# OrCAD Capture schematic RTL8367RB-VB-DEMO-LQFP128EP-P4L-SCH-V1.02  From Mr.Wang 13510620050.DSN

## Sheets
1 01_RTL8367RB-VB_Block_Diagram: title: RTL8367RB-VB Demo-Boaard Block Diagram; rev: v.1.02
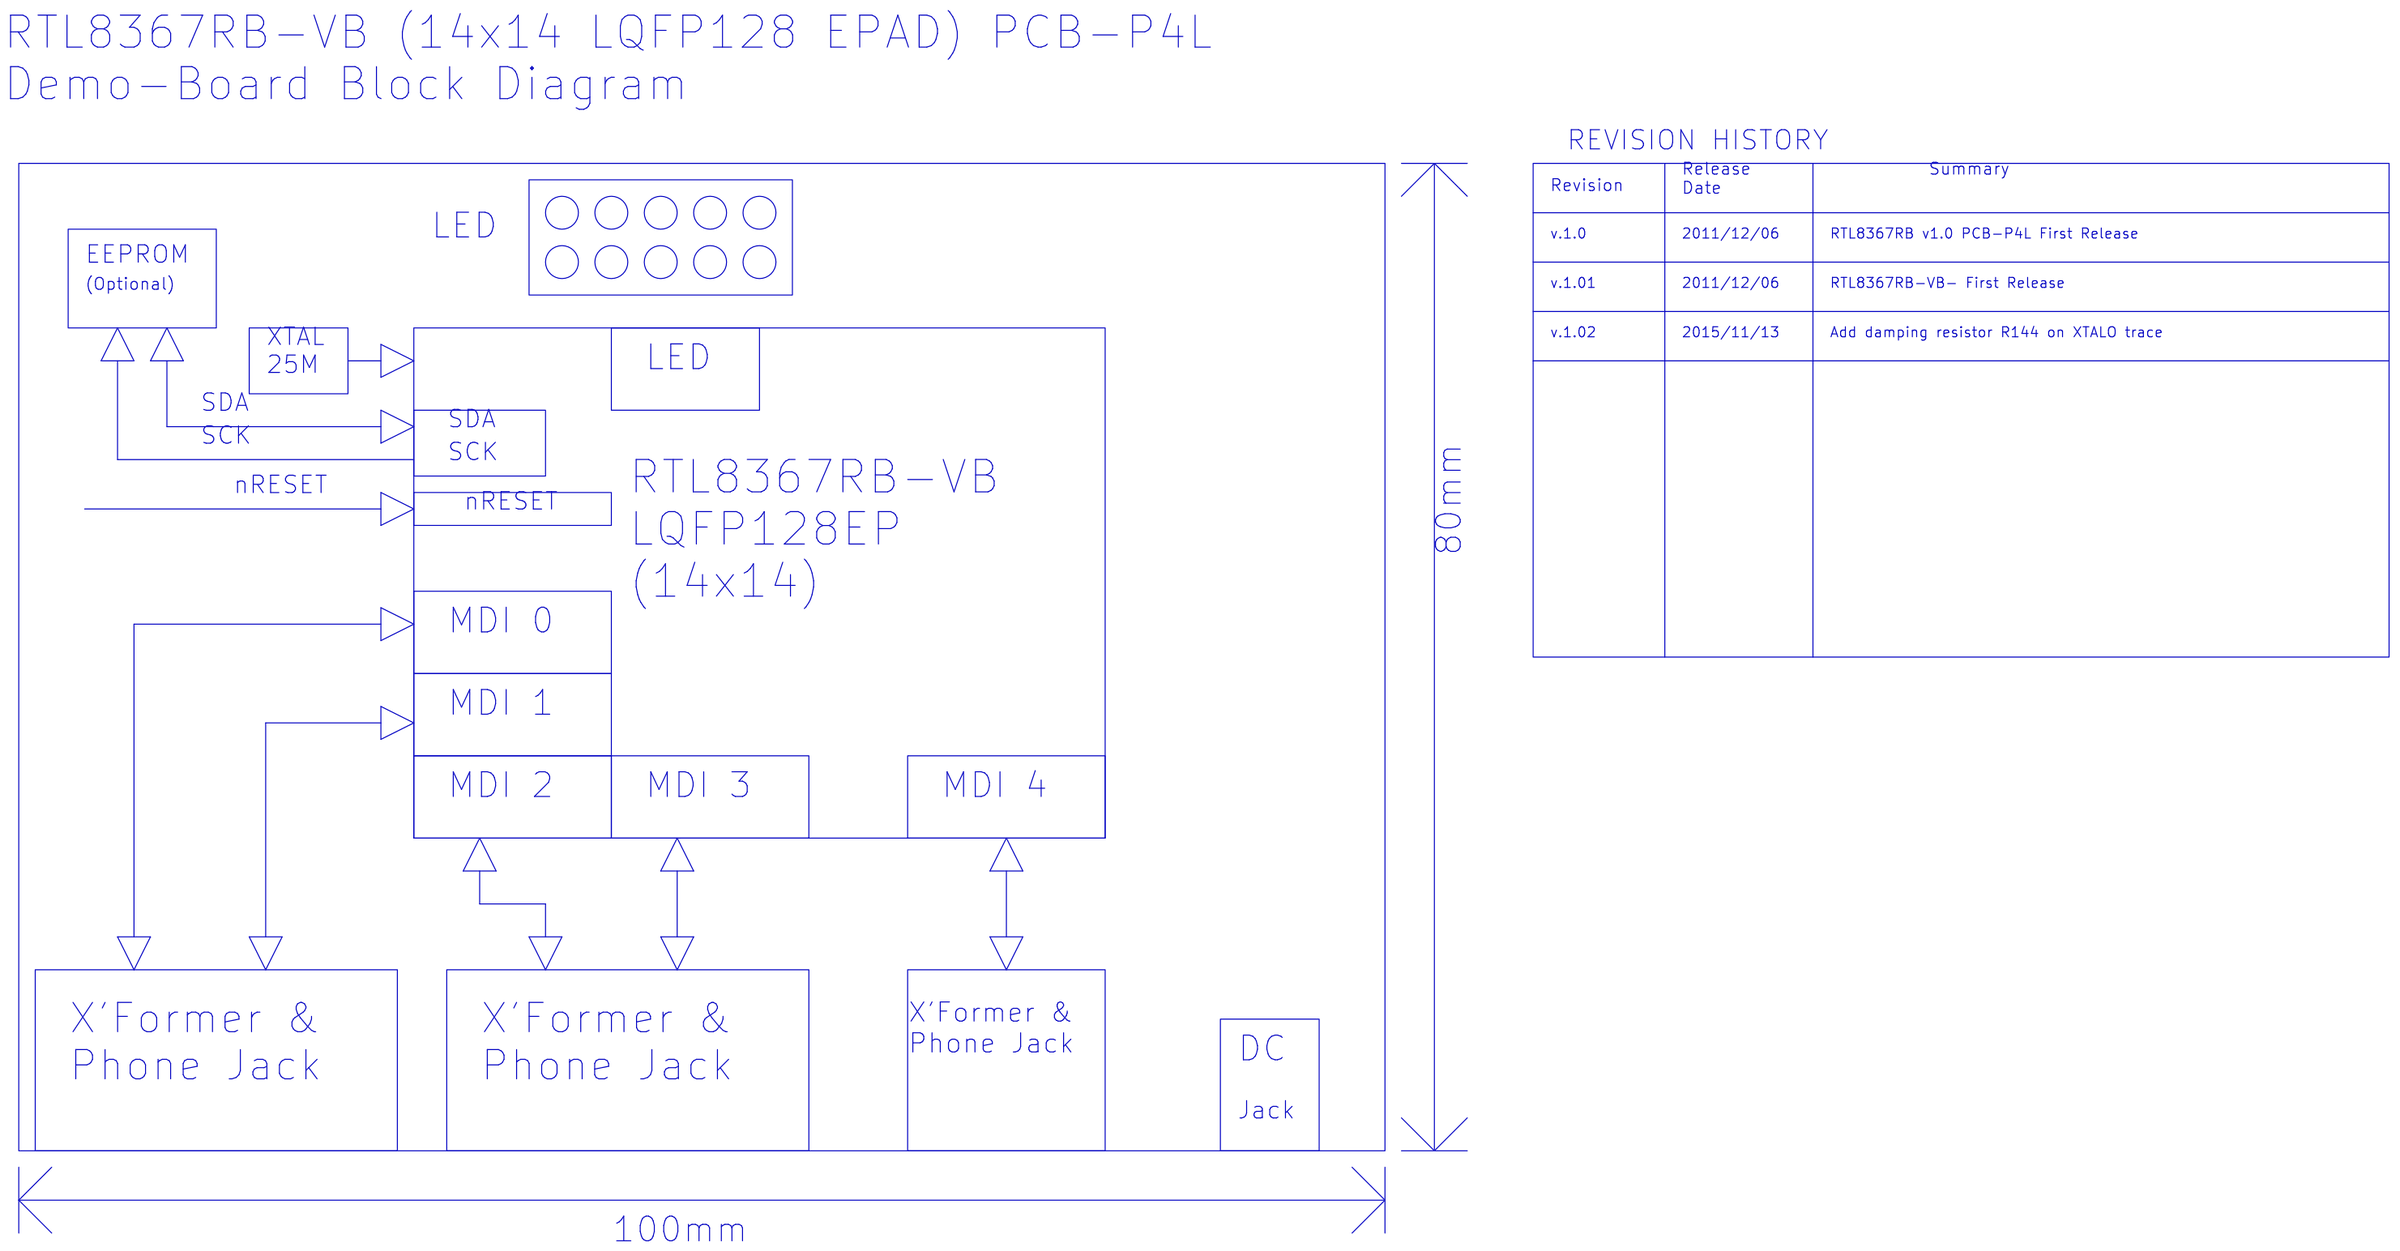
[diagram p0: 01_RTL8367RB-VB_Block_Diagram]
2 02_Power: size B; title: Power
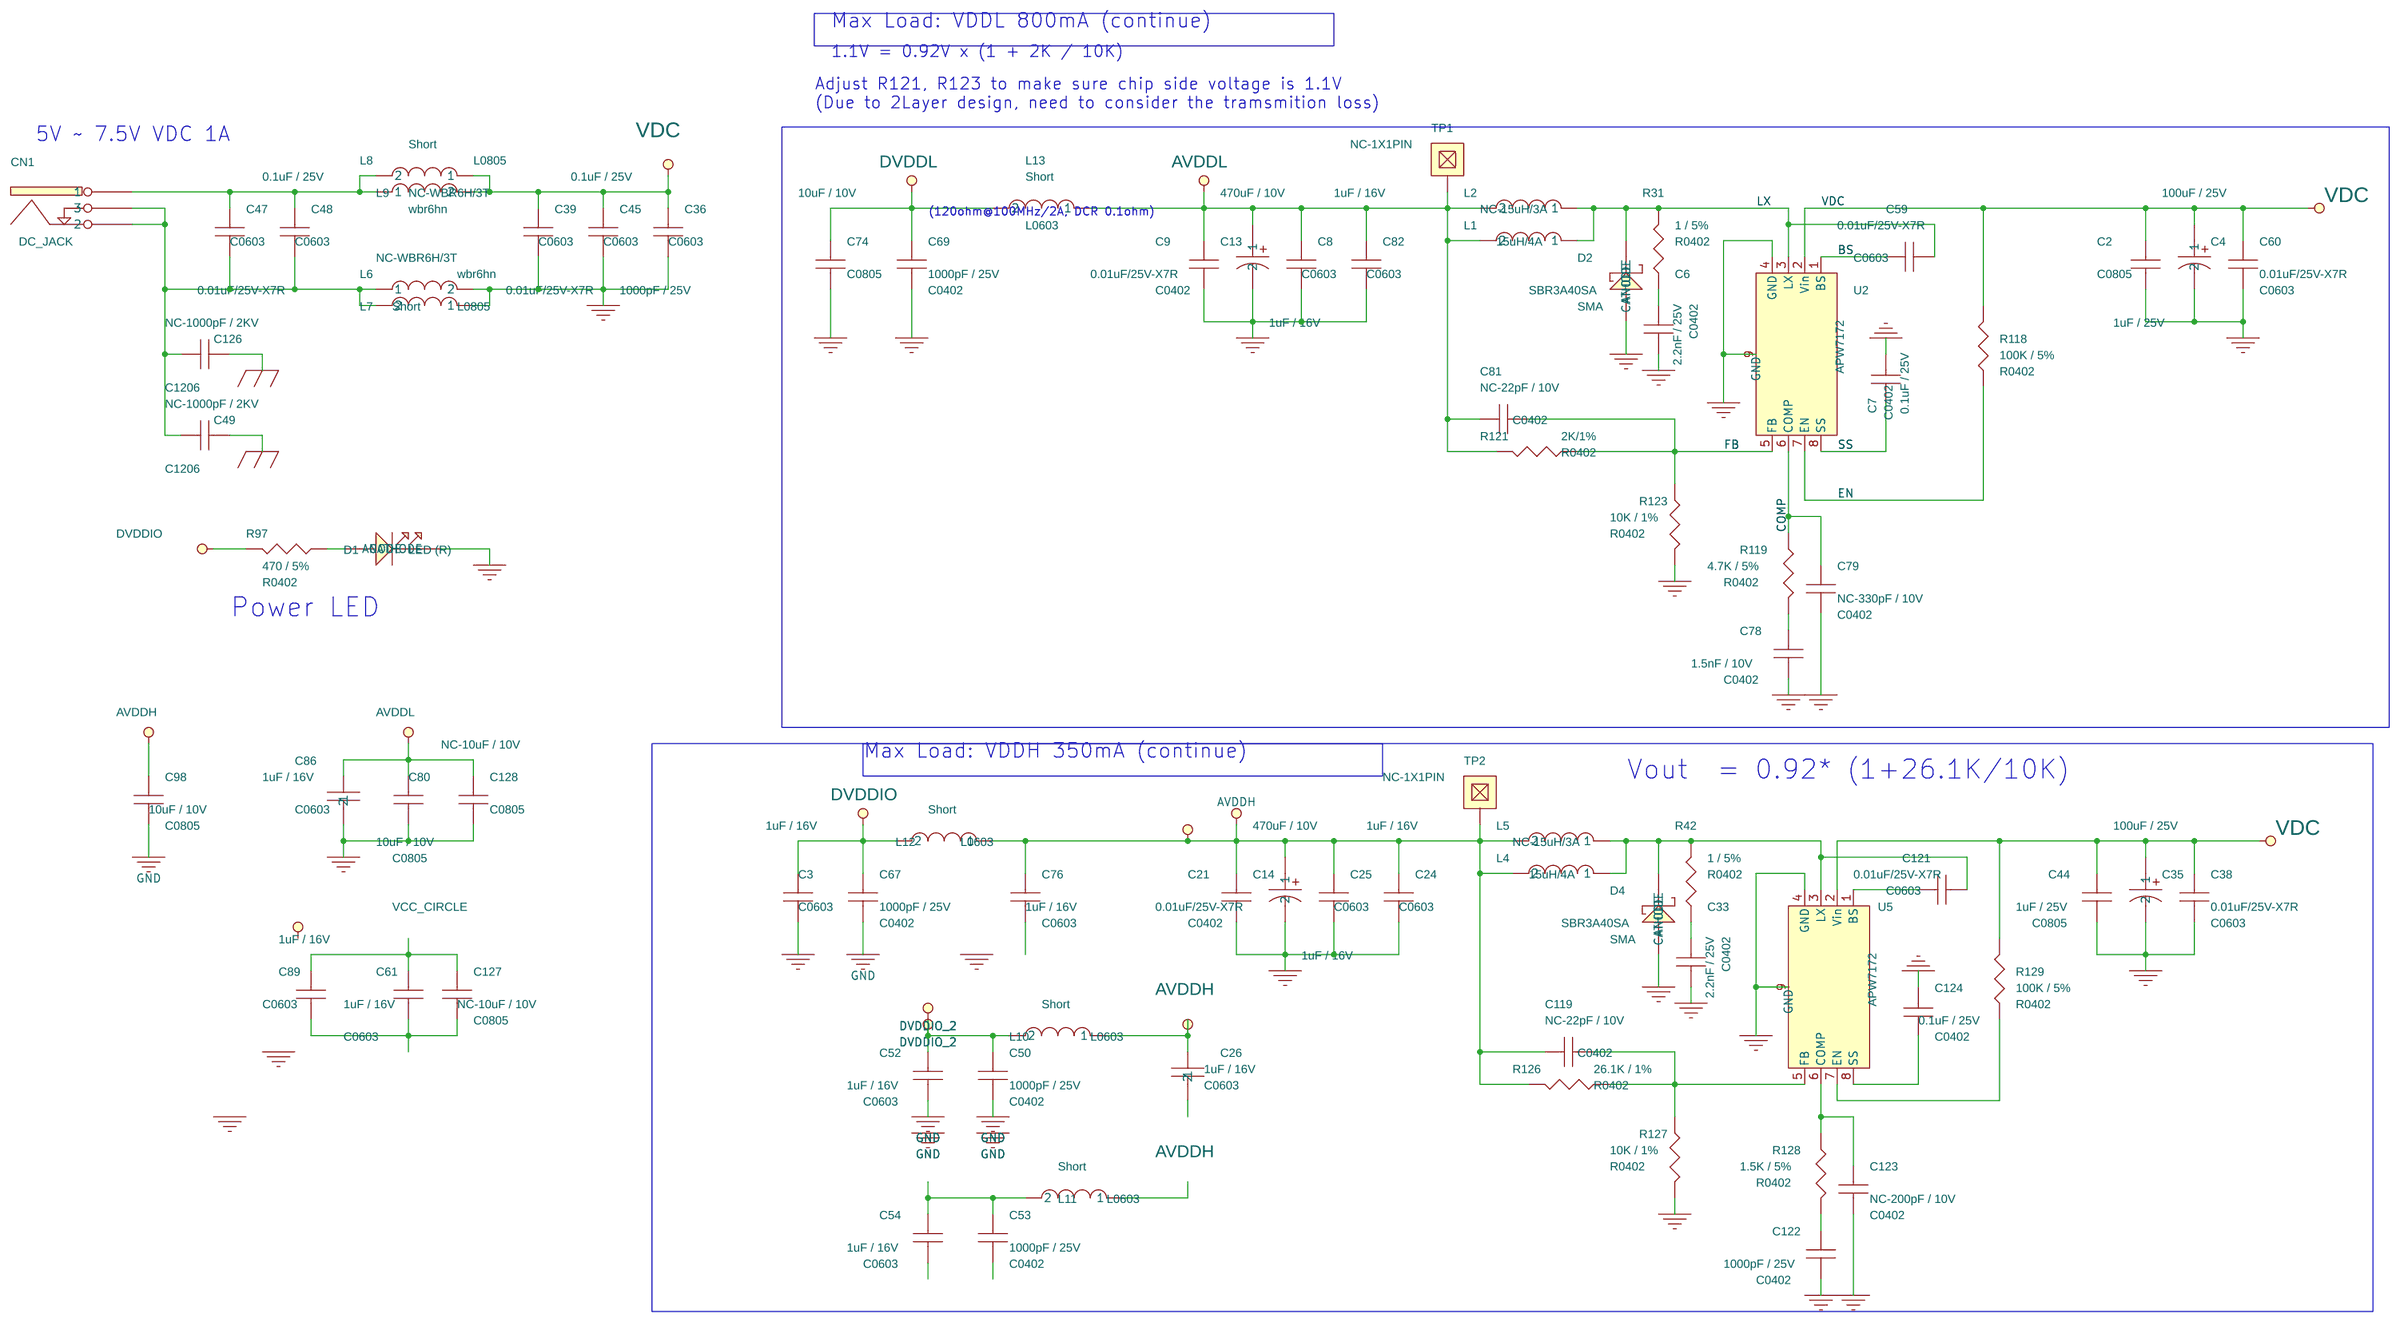
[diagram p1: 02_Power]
3 03_RTL8367RB-VB: size Custom; title: RTL8367RB-VB
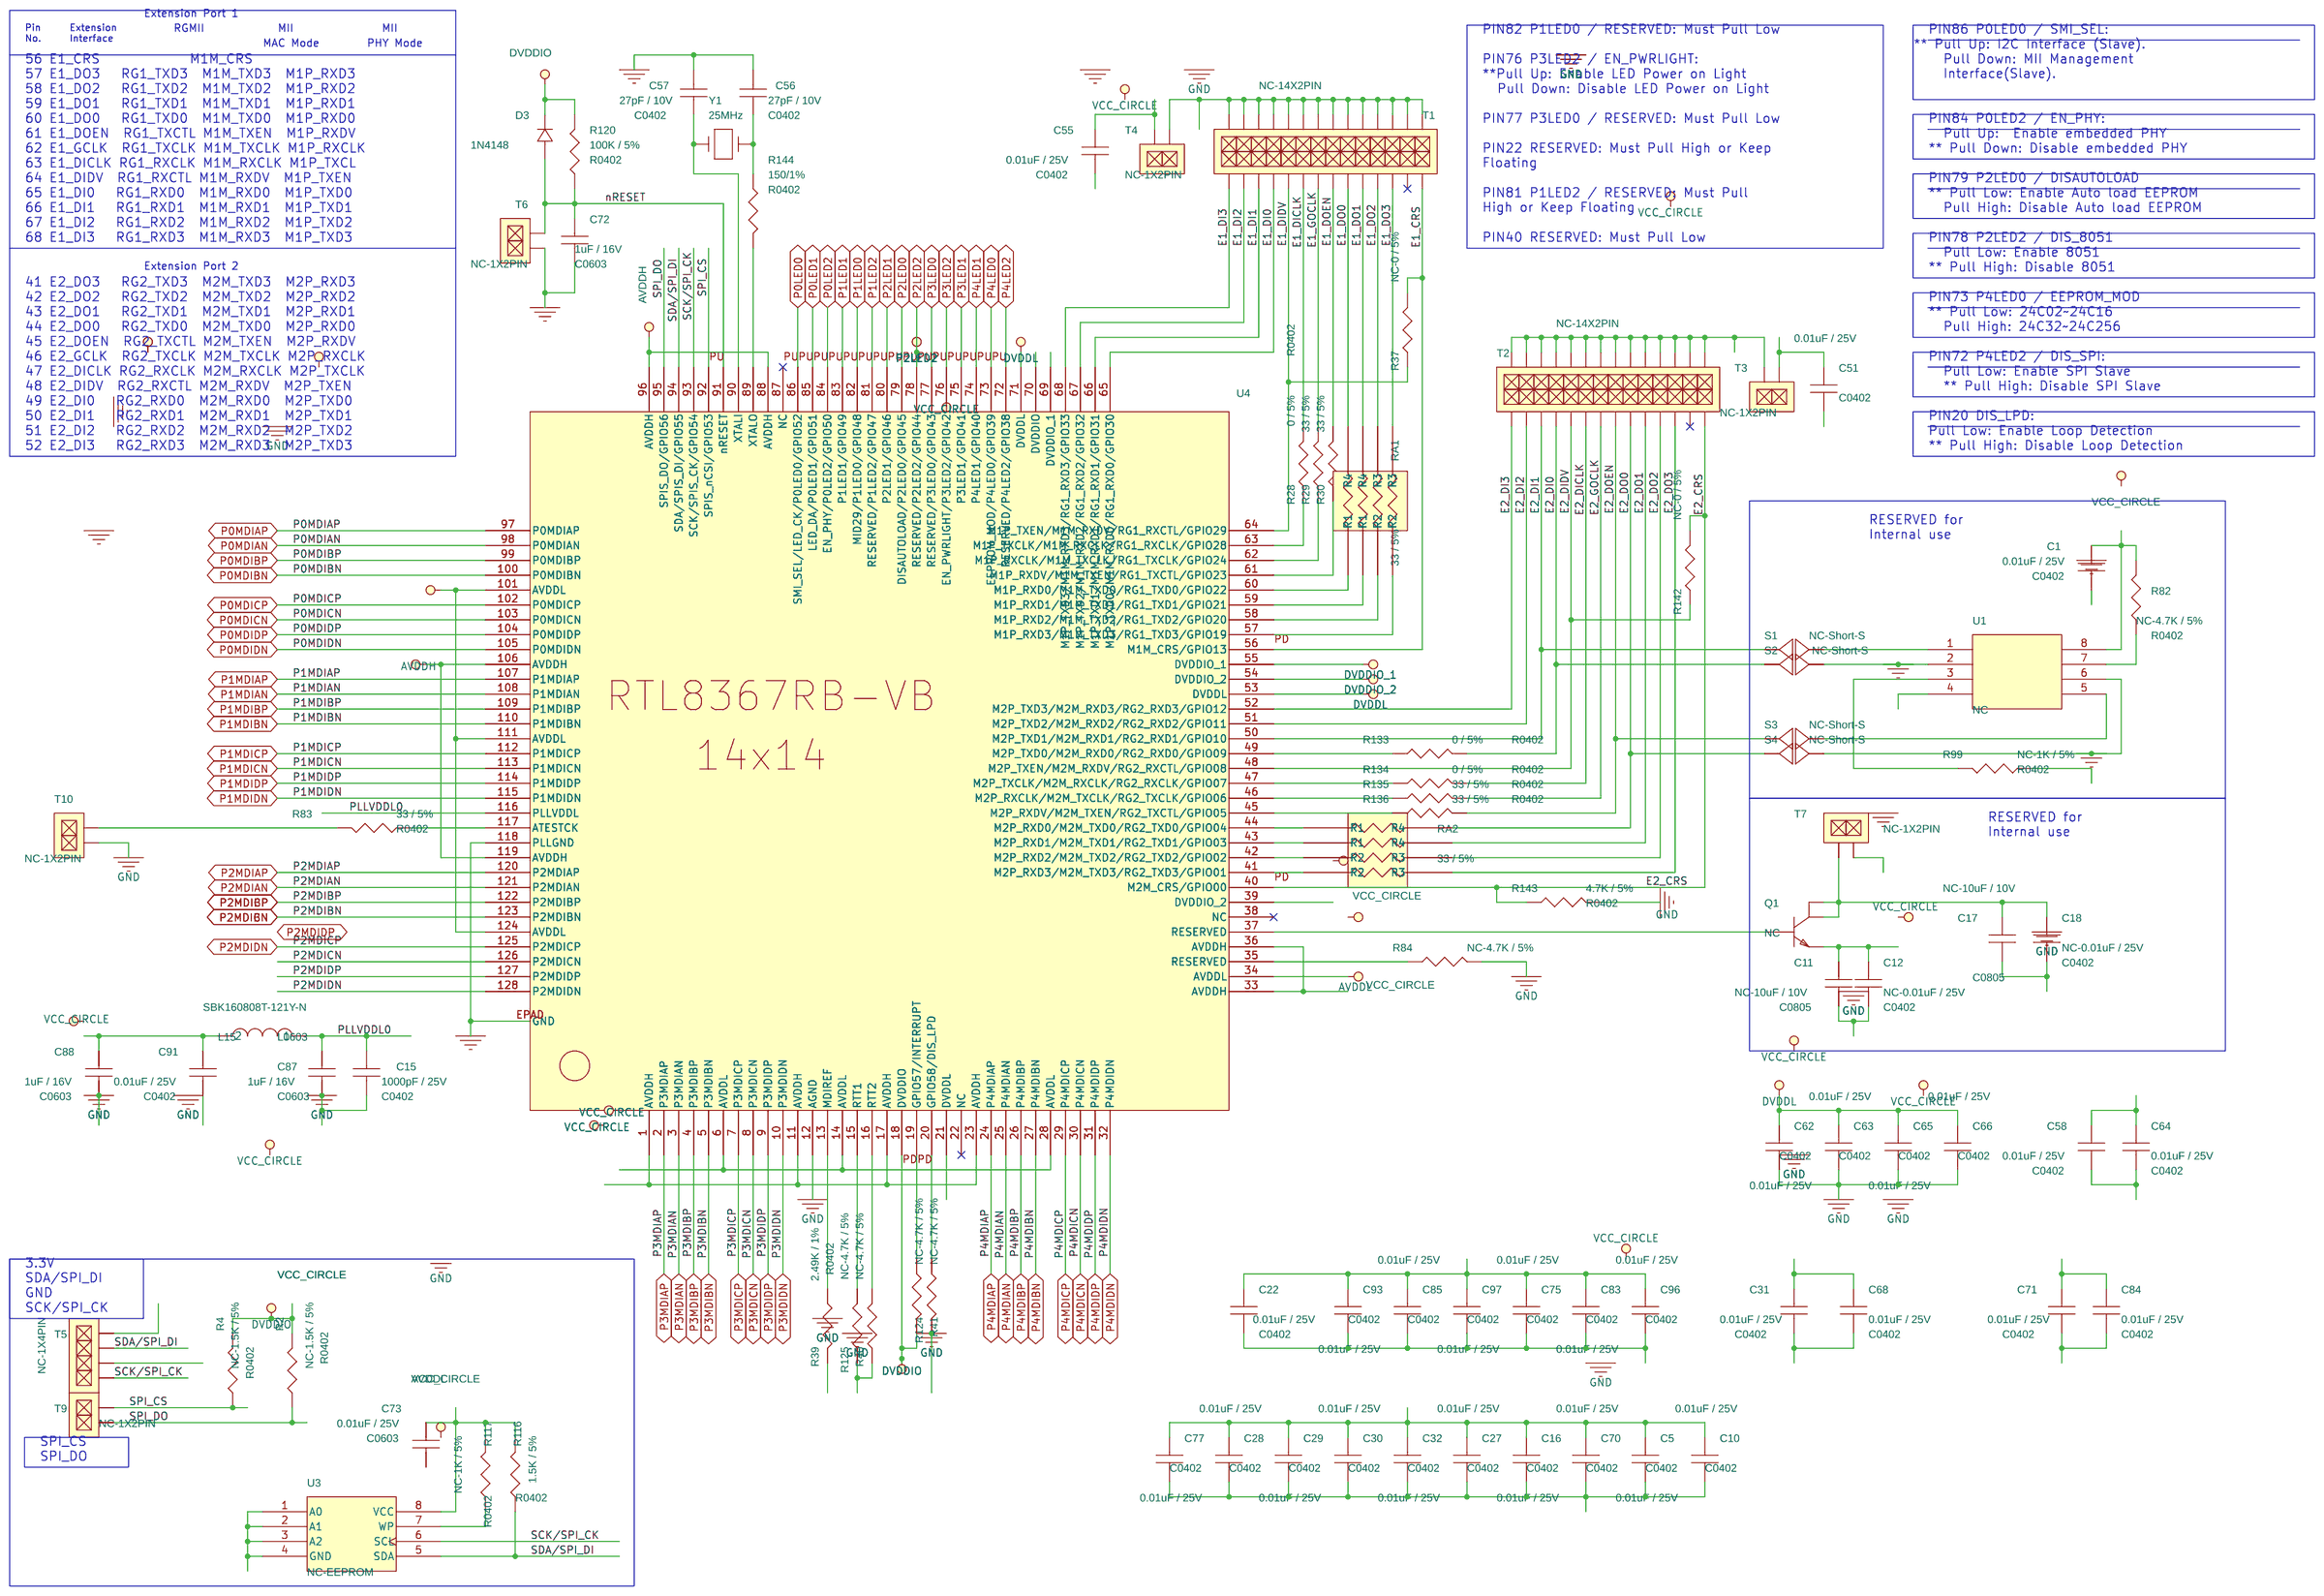
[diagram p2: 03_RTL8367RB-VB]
4 04_RTL8367RB-VB_Transformer: size B; title: RTL8367RB-VB Transformer  & Phonejack
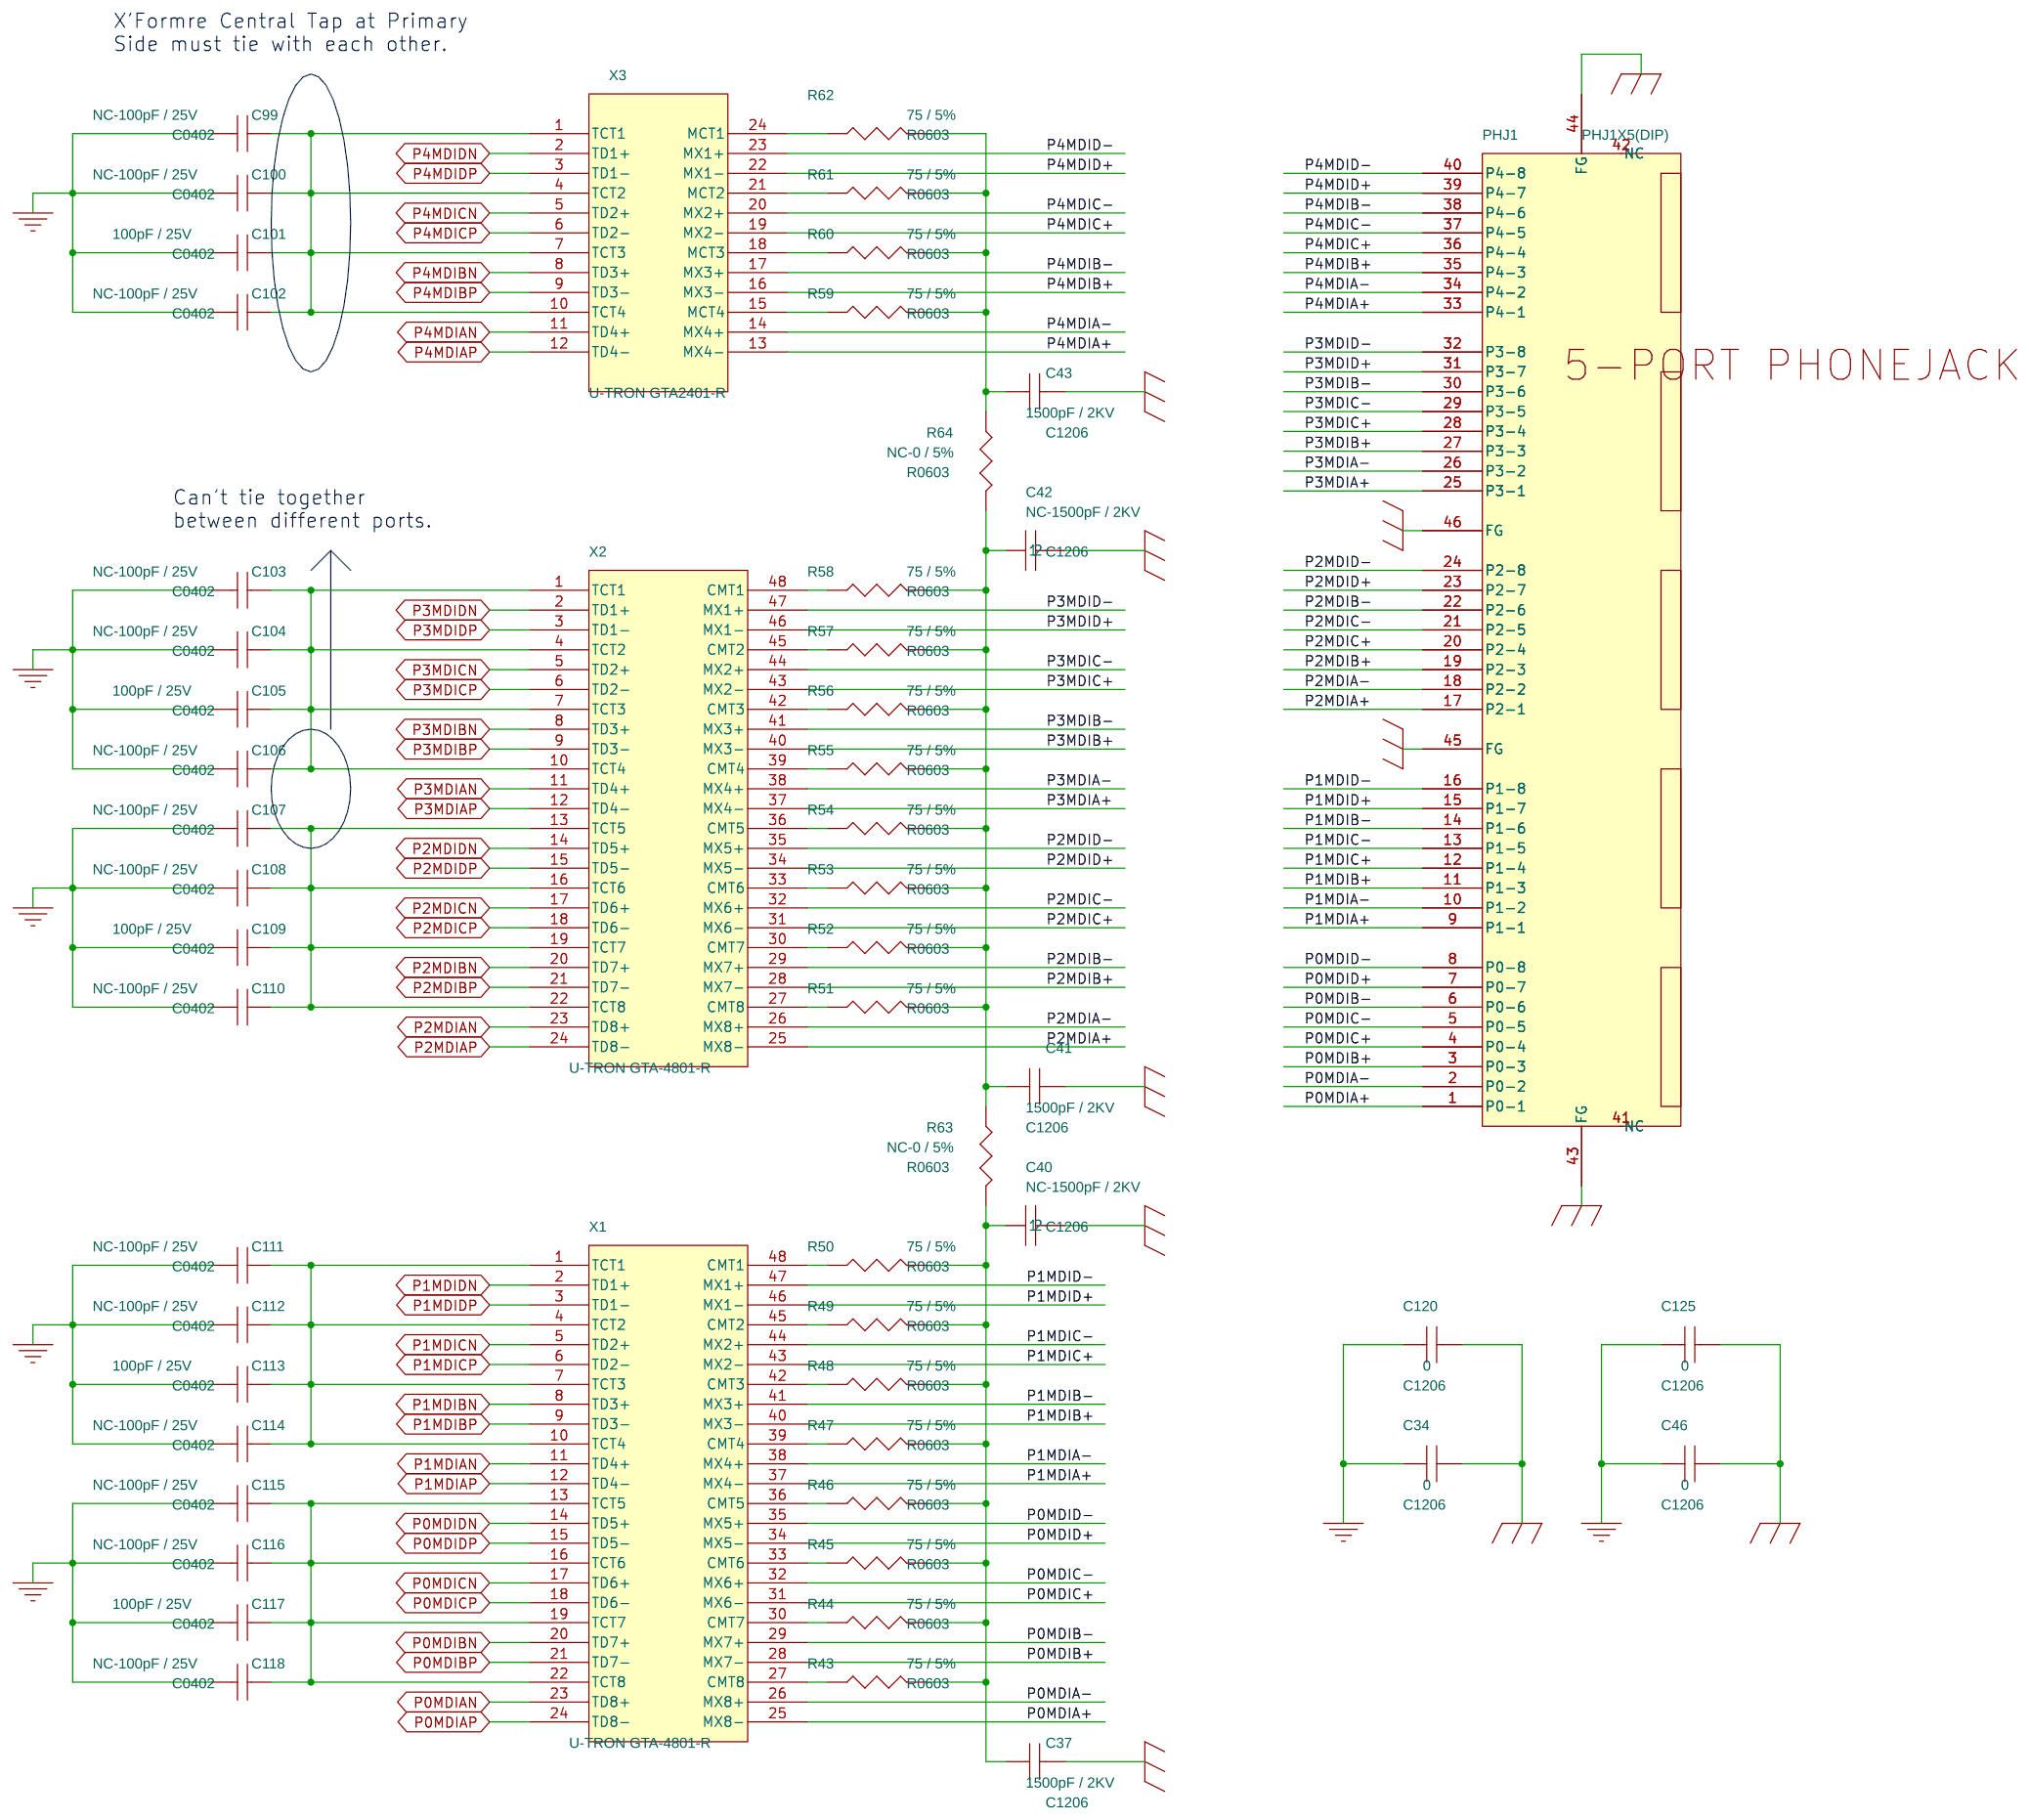
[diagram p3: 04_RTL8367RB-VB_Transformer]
5 05_RTL8367RB-VB_LED: size B; title: RTL8367RB-VB LED
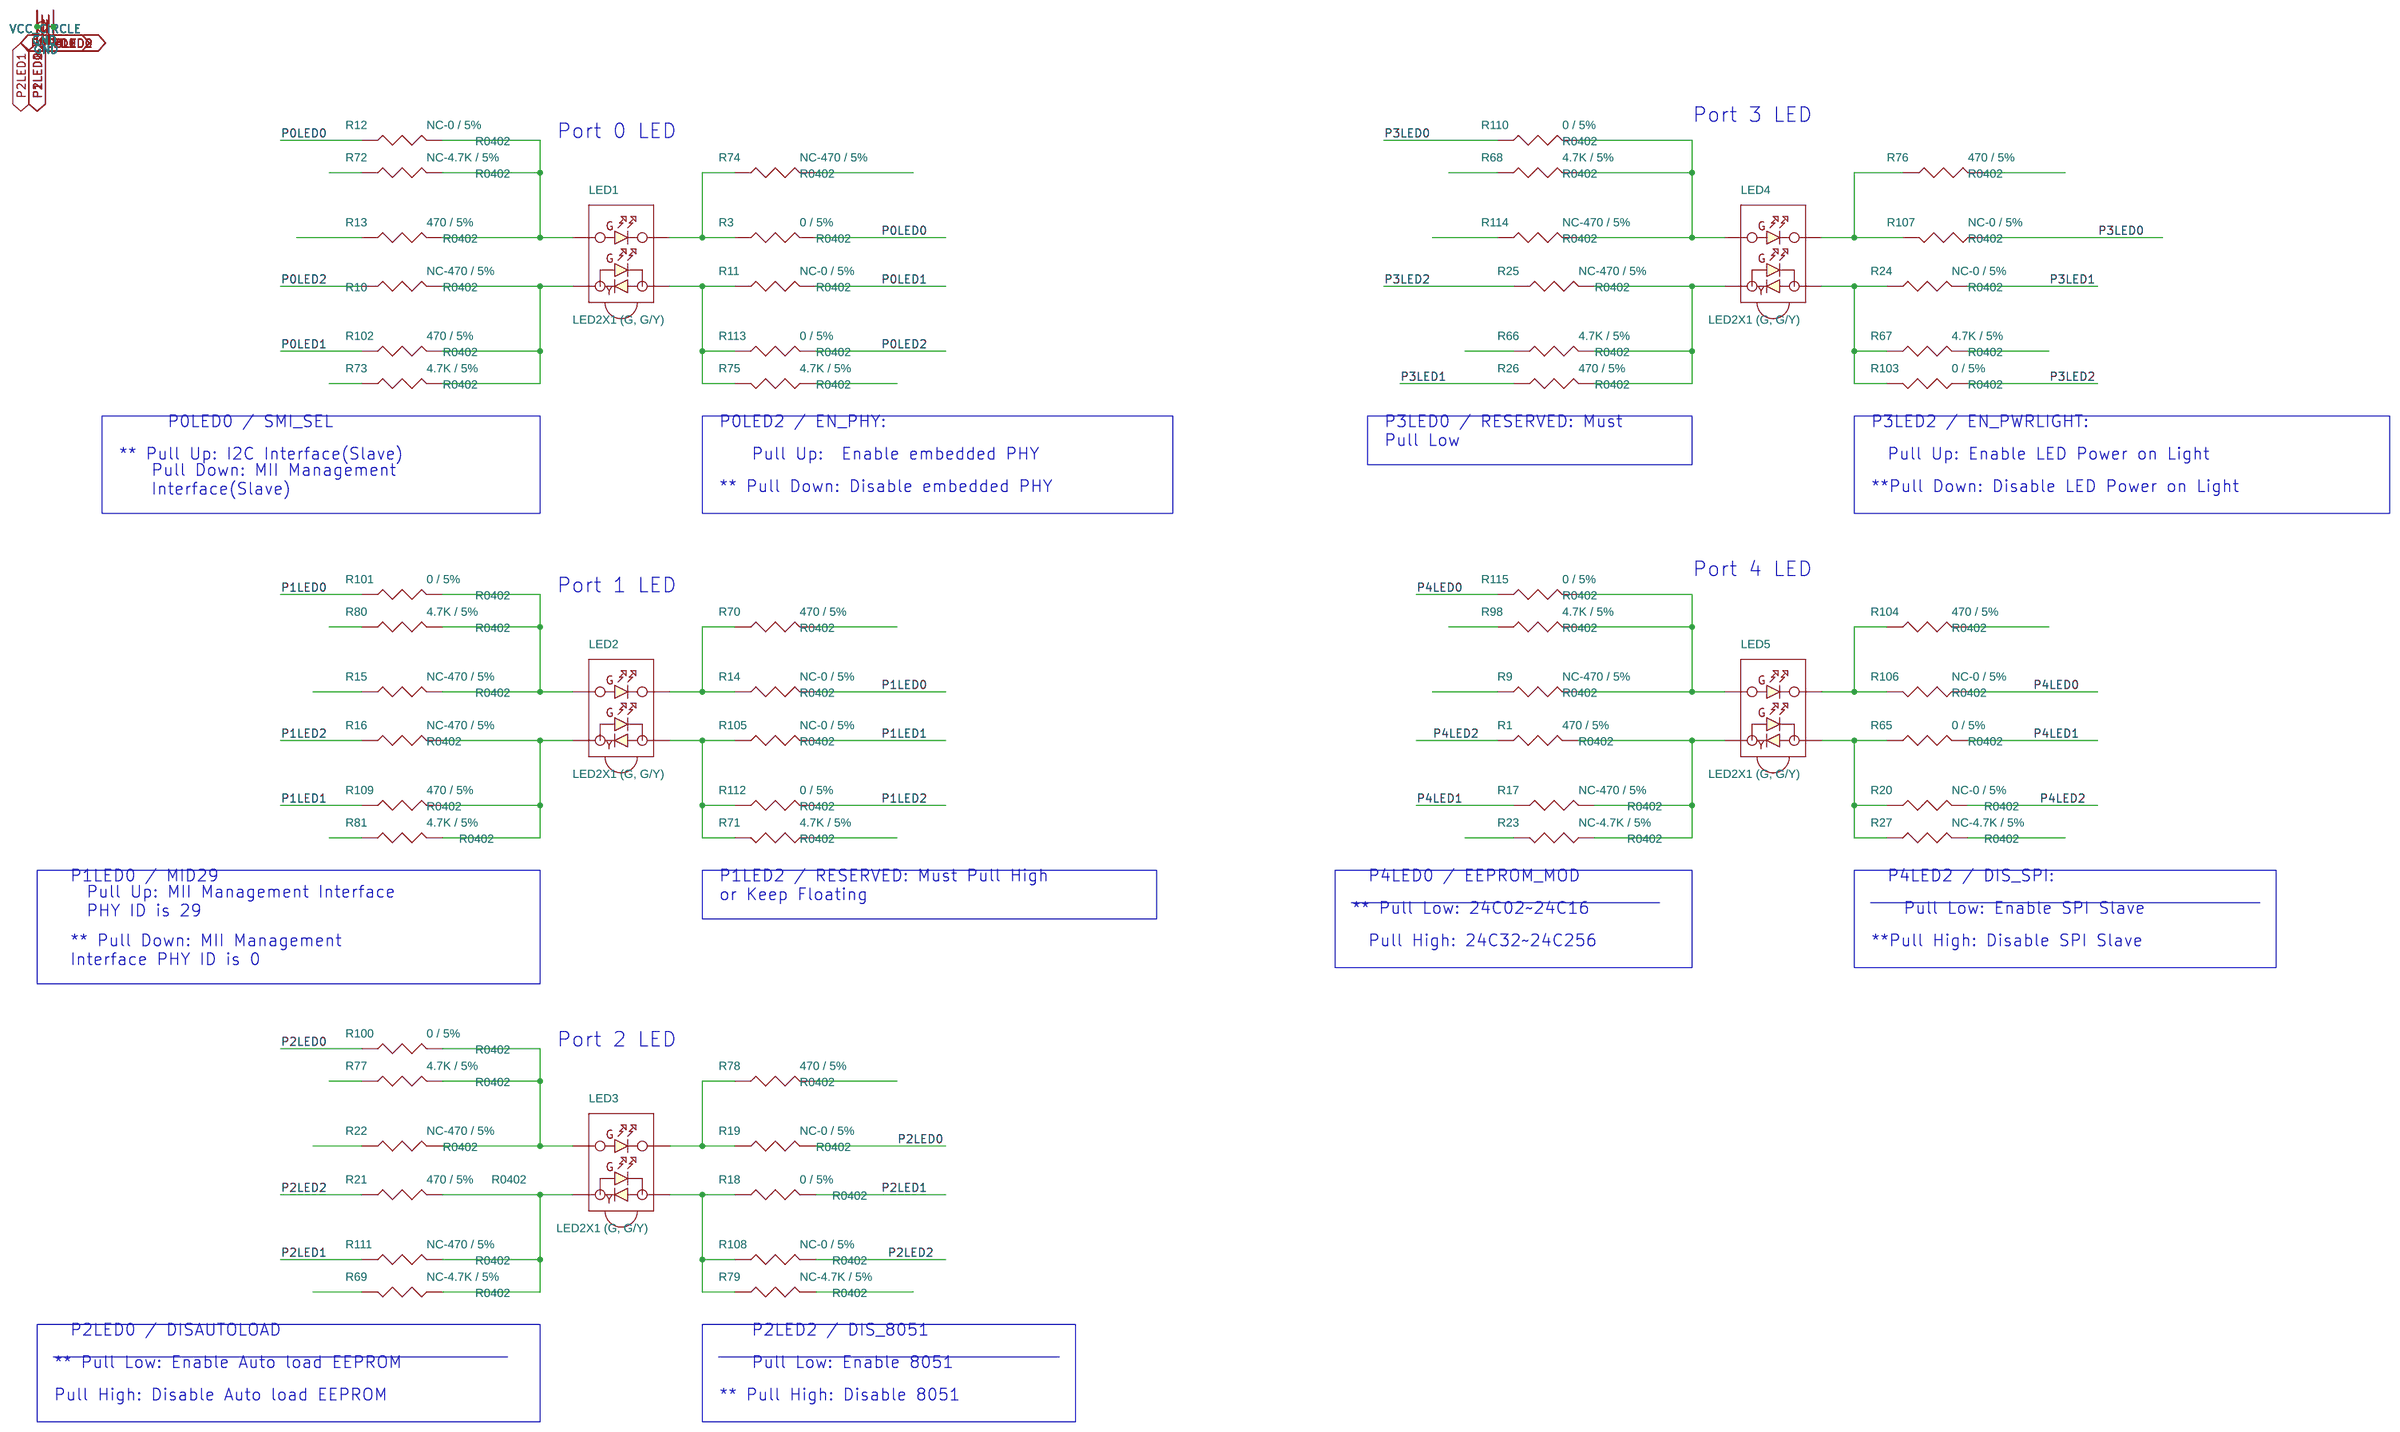
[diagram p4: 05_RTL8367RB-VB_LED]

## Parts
sheet 02_Power
C2  1uF / 25V  [C0805]
C3  1uF / 16V  [C0603]
C4  100uF / 25V  [ECAP150_300]
C6  2.2nF / 25V  [C0402]
C7  0.1uF / 25V  [C0402]
C8  1uF / 16V  [C0603]
C9  0.01uF/25V-X7R  [C0402]
C13  470uF / 10V  [ECAP150_300]
C14  470uF / 10V  [ECAP150_300]
C21  0.01uF/25V-X7R  [C0402]
C24  1uF / 16V  [C0603]
C25  1uF / 16V  [C0603]
C26  1uF / 16V  [C0603]
C33  2.2nF / 25V  [C0402]
C35  100uF / 25V  [ECAP150_300]
C36  1000pF / 25V  [C0603]
C38  0.01uF/25V-X7R  [C0603]
C39  0.01uF/25V-X7R  [C0603]
C44  1uF / 25V  [C0805]
C45  0.1uF / 25V  [C0603]
C47  0.01uF/25V-X7R  [C0603]
C48  0.1uF / 25V  [C0603]
C49  NC-1000pF / 2KV  [C1206]
C50  1000pF / 25V  [C0402]
C52  1uF / 16V  [C0603]
C53  1000pF / 25V  [C0402]
C54  1uF / 16V  [C0603]
C59  0.01uF/25V-X7R  [C0603]
C60  0.01uF/25V-X7R  [C0603]
C61  1uF / 16V  [C0603]
C67  1000pF / 25V  [C0402]
C69  1000pF / 25V  [C0402]
C74  10uF / 10V  [C0805]
C76  1uF / 16V  [C0603]
C78  1.5nF / 10V  [C0402]
C79  NC-330pF / 10V  [C0402]
C80  10uF / 10V  [C0805]
C81  NC-22pF / 10V  [C0402]
C82  1uF / 16V  [C0603]
C86  1uF / 16V  [C0603]
C89  1uF / 16V  [C0603]
C98  10uF / 10V  [C0805]
C119  NC-22pF / 10V  [C0402]
C121  0.01uF/25V-X7R  [C0603]
C122  1000pF / 25V  [C0402]
C123  NC-200pF / 10V  [C0402]
C124  0.1uF / 25V  [C0402]
C126  NC-1000pF / 2KV  [C1206]
C127  NC-10uF / 10V  [C0805]
C128  NC-10uF / 10V  [C0805]
CN1  DC_JACK  [DC_JACK]
D1  LED (R)  [LED]
D2  SBR3A40SA  [SMA]
D4  SBR3A40SA  [SMA]
L1  15uH/4A  [TC4452N_100M]
L2  NC-15uH/3A  [tprh6d38]
L4  15uH/4A  [TC4452N_100M]
L5  NC-15uH/3A  [tprh6d38]
L6  NC-WBR6H/3T  [wbr6hn]
L7  Short  [L0805]
L8  Short  [L0805]
L9  NC-WBR6H/3T  [wbr6hn]
L10  Short  [L0603]
L11  Short  [L0603]
L12  Short  [L0603]
L13  Short  [L0603]
R31  1 / 5%  [R0402]
R42  1 / 5%  [R0402]
R97  470 / 5%  [R0402]
R118  100K / 5%  [R0402]
R119  4.7K / 5%  [R0402]
R121  2K/1%  [R0402]
R123  10K / 1%  [R0402]
R126  26.1K / 1%  [R0402]
R127  10K / 1%  [R0402]
R128  1.5K / 5%  [R0402]
R129  100K / 5%  [R0402]
TP1  NC-1X1PIN  [RL0608N]
TP2  NC-1X1PIN  [RL0608N]
U2  APW7172  [SO-8_gnd]
U5  APW7172  [SO-8_gnd]
sheet 03_RTL8367RB-VB
C1  0.01uF / 25V  [C0402]
C5  0.01uF / 25V  [C0402]
C10  0.01uF / 25V  [C0402]
C11  NC-10uF / 10V  [C0805]
C12  NC-0.01uF / 25V  [C0402]
C15  1000pF / 25V  [C0402]
C16  0.01uF / 25V  [C0402]
C17  NC-10uF / 10V  [C0805]
C18  NC-0.01uF / 25V  [C0402]
C22  0.01uF / 25V  [C0402]
C27  0.01uF / 25V  [C0402]
C28  0.01uF / 25V  [C0402]
C29  0.01uF / 25V  [C0402]
C30  0.01uF / 25V  [C0402]
C31  0.01uF / 25V  [C0402]
C32  0.01uF / 25V  [C0402]
C51  0.01uF / 25V  [C0402]
C55  0.01uF / 25V  [C0402]
C56  27pF / 10V  [C0402]
C57  27pF / 10V  [C0402]
C58  0.01uF / 25V  [C0402]
C62  0.01uF / 25V  [C0402]
C63  0.01uF / 25V  [C0402]
C64  0.01uF / 25V  [C0402]
C65  0.01uF / 25V  [C0402]
C66  0.01uF / 25V  [C0402]
C68  0.01uF / 25V  [C0402]
C70  0.01uF / 25V  [C0402]
C71  0.01uF / 25V  [C0402]
C72  1uF / 16V  [C0603]
C73  0.01uF / 25V  [C0603]
C75  0.01uF / 25V  [C0402]
C77  0.01uF / 25V  [C0402]
C83  0.01uF / 25V  [C0402]
C84  0.01uF / 25V  [C0402]
C85  0.01uF / 25V  [C0402]
C87  1uF / 16V  [C0603]
C88  1uF / 16V  [C0603]
C91  0.01uF / 25V  [C0402]
C93  0.01uF / 25V  [C0402]
C96  0.01uF / 25V  [C0402]
C97  0.01uF / 25V  [C0402]
D3  1N4148  [MLL34]
L15  SBK160808T-121Y-N  [L0603]
Q1  NC  [SOT-89]
R2  NC-1.5K / 5%  [R0402]
R4  NC-1.5K / 5%  [R0402]
R28  0 / 5%  [R0402]
R29  33 / 5%  [R0402]
R30  33 / 5%  [R0402]
R37  NC-0 / 5%  [R0402]
R39  2.49K / 1%  [R0402]
R40  NC-4.7K / 5%  [R0402]
R41  NC-4.7K / 5%  [R0402]
R82  NC-4.7K / 5%  [R0402]
R83  33 / 5%  [R0402]
R84  NC-4.7K / 5%  [R0402]
R99  NC-1K / 5%  [R0402]
R116  1.5K / 5%  [R0402]
R117  NC-1K / 5%  [R0402]
R120  100K / 5%  [R0402]
R124  NC-4.7K / 5%  [R0402]
R125  NC-4.7K / 5%  [R0402]
R133  0 / 5%  [R0402]
R134  0 / 5%  [R0402]
R135  33 / 5%  [R0402]
R136  33 / 5%  [R0402]
R142  NC-0 / 5%  [R0402]
R143  4.7K / 5%  [R0402]
R144  150/1%  [R0402]
RA1  33 / 5%  [8P4r-22]
RA2  33 / 5%  [8P4r-22]
S1  NC-Short-S  [JUO_A_S]
S2  NC-Short-S  [JUO_A_S]
S3  NC-Short-S  [JUO_A_S]
S4  NC-Short-S  [JUO_A_S]
T1  NC-14X2PIN  [header14x2_1_27]
T2  NC-14X2PIN  [header14x2_1_27]
T3  NC-1X2PIN  [SIP_2P]
T4  NC-1X2PIN  [SIP_2P]
T5  NC-1X4PIN  [SIP_4P]
T6  NC-1X2PIN  [SIP_2P]
T7  NC-1X2PIN  [SIP_2P]
T9  NC-1X2PIN  [SIP_2P]
T10  NC-1X2PIN  [SIP_2P]
U1  NC  [SOP8_300]
U3  NC-EEPROM  [DIP8]
U4  RTL8367RB-VB_LQ128EP
Y1  25MHz  [XTAL3]
sheet 04_RTL8367RB-VB_Transformer
C34  0  [C1206]
C37  1500pF / 2KV  [C1206]
C40  NC-1500pF / 2KV  [C1206]
C41  1500pF / 2KV  [C1206]
C42  NC-1500pF / 2KV  [C1206]
C43  1500pF / 2KV  [C1206]
C46  0  [C1206]
C99  NC-100pF / 25V  [C0402]
C100  NC-100pF / 25V  [C0402]
C101  100pF / 25V  [C0402]
C102  NC-100pF / 25V  [C0402]
C103  NC-100pF / 25V  [C0402]
C104  NC-100pF / 25V  [C0402]
C105  100pF / 25V  [C0402]
C106  NC-100pF / 25V  [C0402]
C107  NC-100pF / 25V  [C0402]
C108  NC-100pF / 25V  [C0402]
C109  100pF / 25V  [C0402]
C110  NC-100pF / 25V  [C0402]
C111  NC-100pF / 25V  [C0402]
C112  NC-100pF / 25V  [C0402]
C113  100pF / 25V  [C0402]
C114  NC-100pF / 25V  [C0402]
C115  NC-100pF / 25V  [C0402]
C116  NC-100pF / 25V  [C0402]
C117  100pF / 25V  [C0402]
C118  NC-100pF / 25V  [C0402]
C120  0  [C1206]
C125  0  [C1206]
PHJ1  PHJ1X5(DIP)  [rj45x5]
R43  75 / 5%  [R0603]
R44  75 / 5%  [R0603]
R45  75 / 5%  [R0603]
R46  75 / 5%  [R0603]
R47  75 / 5%  [R0603]
R48  75 / 5%  [R0603]
R49  75 / 5%  [R0603]
R50  75 / 5%  [R0603]
R51  75 / 5%  [R0603]
R52  75 / 5%  [R0603]
R53  75 / 5%  [R0603]
R54  75 / 5%  [R0603]
R55  75 / 5%  [R0603]
R56  75 / 5%  [R0603]
R57  75 / 5%  [R0603]
R58  75 / 5%  [R0603]
R59  75 / 5%  [R0603]
R60  75 / 5%  [R0603]
R61  75 / 5%  [R0603]
R62  75 / 5%  [R0603]
R63  NC-0 / 5%  [R0603]
R64  NC-0 / 5%  [R0603]
X1  U-TRON GTA-4801-R  [G2P109N]
X2  U-TRON GTA-4801-R  [G2P109N]
X3  U-TRON GTA2401-R  [g241xxdu]
sheet 05_RTL8367RB-VB_LED
LED1  LED2X1 (G, G/Y)  [LED_2L_100]
LED2  LED2X1 (G, G/Y)  [LED_2L_100]
LED3  LED2X1 (G, G/Y)  [LED_2L_100]
LED4  LED2X1 (G, G/Y)  [LED_2L_100]
LED5  LED2X1 (G, G/Y)  [LED_2L_100]
R1  470 / 5%  [R0402]
R3  0 / 5%  [R0402]
R9  NC-470 / 5%  [R0402]
R10  NC-470 / 5%  [R0402]
R11  NC-0 / 5%  [R0402]
R12  NC-0 / 5%  [R0402]
R13  470 / 5%  [R0402]
R14  NC-0 / 5%  [R0402]
R15  NC-470 / 5%  [R0402]
R16  NC-470 / 5%  [R0402]
R17  NC-470 / 5%  [R0402]
R18  0 / 5%  [R0402]
R19  NC-0 / 5%  [R0402]
R20  NC-0 / 5%  [R0402]
R21  470 / 5%  [R0402]
R22  NC-470 / 5%  [R0402]
R23  NC-4.7K / 5%  [R0402]
R24  NC-0 / 5%  [R0402]
R25  NC-470 / 5%  [R0402]
R26  470 / 5%  [R0402]
R27  NC-4.7K / 5%  [R0402]
R65  0 / 5%  [R0402]
R66  4.7K / 5%  [R0402]
R67  4.7K / 5%  [R0402]
R68  4.7K / 5%  [R0402]
R69  NC-4.7K / 5%  [R0402]
R70  470 / 5%  [R0402]
R71  4.7K / 5%  [R0402]
R72  NC-4.7K / 5%  [R0402]
R73  4.7K / 5%  [R0402]
R74  NC-470 / 5%  [R0402]
R75  4.7K / 5%  [R0402]
R76  470 / 5%  [R0402]
R77  4.7K / 5%  [R0402]
R78  470 / 5%  [R0402]
R79  NC-4.7K / 5%  [R0402]
R80  4.7K / 5%  [R0402]
R81  4.7K / 5%  [R0402]
R98  4.7K / 5%  [R0402]
R100  0 / 5%  [R0402]
R101  0 / 5%  [R0402]
R102  470 / 5%  [R0402]
R103  0 / 5%  [R0402]
R104  470 / 5%  [R0402]
R105  NC-0 / 5%  [R0402]
R106  NC-0 / 5%  [R0402]
R107  NC-0 / 5%  [R0402]
R108  NC-0 / 5%  [R0402]
R109  470 / 5%  [R0402]
R110  0 / 5%  [R0402]
R111  NC-470 / 5%  [R0402]
R112  0 / 5%  [R0402]
R113  0 / 5%  [R0402]
R114  NC-470 / 5%  [R0402]
R115  0 / 5%  [R0402]

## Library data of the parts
C2 C44 = CAP_NP: Package: 0805; Vendor: Walsin Technology Corp.; Vendor PN: 0805F105M250CT
C3 C8 C24 C25 C52 C54 C61 C72 C76 C82 C87-C89 = CAP_NP: Package: 0603; Vendor: Walsin Technology Corp.; Vendor PN: 0603F105M160CT
C4 = C_v2_1: Package: 6x11; Vendor: Gemmy Electronics Co., Ltd.; Vendor PN: GHR100M025-0611B
C6 C33 = CAP_NP: Package: 0402; Vendor: Walsin Technology Corp.; Vendor PN: 0402B222K250CT
C7 C45 C48 C124 = CAP_NP: Package: 0402; Vendor: Walsin Technology Corp.; Vendor PN: 0402F104Z250CT
C9 C21 C38 C39 C47 C59 C60 C121 = CAP_NP: Package: 0402; Part Number: 0402B103K250CT; Vendor: Walsin Technology Corp.
C13 = C_v2: Package: 6x11; Vendor: Gemmy Electronics Co., Ltd.; Vendor PN: GHR470M010-0611B
C14 = C_v2_2: Package: 6x11; Vendor: Gemmy Electronics Co., Ltd.; Vendor PN: GHR470M010-0611B
C26 = C_1: Package: 0603; Vendor: Walsin Technology Corp.; Vendor PN: 0603F105M160CT
C35 = C_v2_3: Package: 6x11; Vendor: Gemmy Electronics Co., Ltd.; Vendor PN: GHR100M025-0611B
C15 C36 C50 C53 C67 C69 C122 = CAP_NP: Package: 0402; Vendor: Walsin Technology Corp.; Vendor PN: 0402B102K250CT
C34 C46 C49 C120 C125 C126 = CAP_NP: Package: 1206; Vendor: Walsin Technology Corp.; Vendor PN: 1206B102K202CT
C11 C17 C74 C80 C98 C127 C128 = CAP_NP: Package: 0805; Vendor: Walsin Technology Corp.; Vendor PN: 0805F106Z100CT
C78 = CAP_NP: Package: 0402; Vendor: Walsin Technology Corp.; Vendor PN: 0402B152K100CT
C79 = CAP_NP: Package: 0402; Vendor: Walsin Technology Corp.; Vendor PN: 0402B331K100CT
C81 C119 = CAP_NP: Package: 0402; Vendor: Walsin Technology Corp.; Vendor PN: 0402N220J100CT
C86 = C: Package: 0603; Vendor: Walsin Technology Corp.; Vendor PN: 0603F105M160CT
C123 = CAP_NP: Package: 0402; Vendor: Walsin Technology Corp.; Vendor PN: 0402N201J160LT
CN1 = POWERJACK: 5PIN Power Connector; Part No: JK-DC-031
D1 = LED_6: Package: KTL-33x-1; Part Number: KTL-33P-1; Vendor: KUANG TIEN Electronic Corp.
D2 D4 = DIODE_SCHOTTKY_0: DIODE 1N5817,DIP, 20V, 1A; Part No: DD-1N5819-D-T; Vendor: DIODES Incorporated.
L1 = INDUCTOR_0_2: Package: TC4452N; Vendor: Mingstar Electronic Corp.; Vendor PN: TC4452N-150M
L2 = INDUCTOR_0_1
L4 = INDUCTOR_0_3: Package: TC4452N; Vendor: Mingstar Electronic Corp.; Vendor PN: TC4452N-150M
L5 = INDUCTOR_0
L6 = L_5: Vendor: Mingstar Electronic Corp.; Vendor PN: WBR6H/3T
L7 = L_2: Package: 0805; Vendor: Walsin Technology Corp.; Vendor PN: WR08X000 PTL
L8 = L_4: Package: 0805; Vendor: Walsin Technology Corp.; Vendor PN: WR08X000 PTL
L9 = L_3: Vendor: Mingstar Electronic Corp.; Vendor PN: WBR6H/3T
L10 = L_1: Package: 0603; Vendor: Chilisin Electronics Corp.; Vendor PN: SBK160808T-121Y-N
L11 = L_7: Package: 0603; Vendor: Walsin Technology Corp.; Vendor PN: WR06X000 PTL
L12 = L_6: Package: 0603; Vendor: Chilisin Electronics Corp.; Vendor PN: SBK160808T-121Y-N
L13 = L: Package: 0603; Vendor: Chilisin Electronics Corp.; Vendor PN: SBK160808T-121Y-N
R31 R42 = R: Package: 0402; Vendor: Walsin Technology Corp.; Vendor PN: WR04X1R0 JTL
R1 R9 R10 R13 R15-R17 R21 R22 R25 R26 R70 R74 R76 R78 R97 R102 R104 R109 R111 R114 = R: Package: 0402; Vendor: Walsin Technology Corp.; Vendor PN: WR04X471 JTL
R118 R120 R129 = R: Package: 0402; Vendor: Walsin Technology Corp.; Vendor PN: WR04X104 JTL
R23 R27 R40 R41 R66-R69 R71-R73 R75 R77 R79-R82 R84 R98 R119 R124 R125 R143 = R: Package: 0402; Vendor: Walsin Technology Corp.; Vendor PN: WR04X472 JTL
R121 = R: Package: 0402; Part Number: WR04X2001 FTL; Vendor: Walsin Technology Corp.
R123 R127 = R: Package: 0402; Vendor: Walsin Technology Corp.; Vendor PN: WR04X1002FTL
R126 = R: Package: 0402; Vendor: Walsin Technology Corp.; Vendor PN: WR04X2612FTL
R2 R4 R116 R128 = R: Package: 0402; Vendor: Walsin Technology Corp.; Vendor PN: WR04X152 JTL
TP1 TP2 = 1X1PIN
U2 U5 = APW7172: Package: SOP-8; Vendor: Anpec Electronics Corp.; Vendor PN: APW7172 K
C1 C5 C10 C12 C16 C18 C22 C27-C32 C51 C55 C58 C62-C66 C68 C70 C71 C73 C75 C77 C83-C85 C91 C93 C96 C97 = CAP_NP: Package: 0402; Vendor: Walsin Technology Corp.; Vendor PN: 0402F103Z250CT
C56 C57 = CAP_NP: Package: 0402; Vendor: Walsin Technology Corp.; Vendor PN: 0402N270J100CT
D3 = D1N4148: Package: SOD123; Vendor: DIODES Incorporated.; Vendor PN: 1N4148W-7-F
L15 = L: Package: 0603; Vendor: Chilisin Electronics Corp.
Q1 = 2SD266_2: Vendor: DIODES Incorporated.; Vendor PN: 2DD2678
R3 R11 R12 R14 R18-R20 R24 R28 R37 R65 R100 R101 R103 R105-R108 R110 R112 R113 R115 R133 R134 R142 = R: Package: 0402; Vendor: Walsin Technology Corp.; Vendor PN: WR04X000 PTL
R29 R30 R83 R135 R136 = R: Package: 0402; Vendor: Walsin Technology Corp.; Vendor PN: WR04X330 JTL
R39 = R: Package: 0402; Vendor: Walsin Technology Corp.; Vendor PN: WR04X2491FTL
R99 R117 = R: Package: 0402; Vendor: Walsin Technology Corp.; Vendor PN: WR04X102 JTL
R144 = R: Package: 0402; Part Number: WR04X151 JTL; Vendor: Walsin Technology Corp.
RA1 RA2 = 8P4R_0: Package: 0402x4; Vendor: Walsin Technology Corp.; Vendor PN: WA04X330 JTL
S1-S4 = Short_Pad
T1 T2 = 14x2PIN
T3 T4 T6 T7 T9 T10 = 1x2PIN_0: Vendor: HEADER
T5 = 1X3PIN_0: Vendor: HEADER
U1 = 24C04A_SO8_1: Package: SOP-8
U3 = 24C04A_SO8_0
U4 = vRTL8367RB-VB_LQ128EP_1
Y1 = CRYSTAL: Package: HC-49US; Vendor: YOKETAN Corp.; Vendor PN: R49SDA-025000-F20-YYD-YRA
C37 C41 C43 = CAP_NP: Package: 1206; Vendor: Walsin Technology Corp.; Vendor PN: 1206B152K202CT
C40 = C_1: Package: 1206; Vendor: Walsin Technology Corp.; Vendor PN: 1206B152K202CT
C42 = C: Package: 1206; Vendor: Walsin Technology Corp.; Vendor PN: 1206B152K202CT
C99-C118 = CAP_NP: Package: 0402; Vendor: Walsin Technology Corp.; Vendor PN: 0402B101K250CT
PHJ1 = PHJ8X8_1
R43-R62 = R: Package: 0603; Vendor: Walsin Technology Corp.; Vendor PN: WR06X750 JTL
R63 R64 = R: Package: 0603; Vendor: Walsin Technology Corp.; Vendor PN: WR06X000 PTL
X1 X2 = 1000Base-T_DualPort_Xformer_0: Vendor: U-TRON Electronics Co., Ltd.
X3 = H5007: Vendor: U-TRON Electronics Co., Ltd.
LED1-LED5 = LED3X1_2: Package: KTL-31xx-2; Part Number: KTL-31(G/GYW)-2; Vendor: KUANG TIEN Electronic Corp.

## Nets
AVDDH: C5.1 C10.1 C14.1 C16.1 C21.1 C24.1 C25.1 C26.1 C27.1 C28.1 C29.1 C30.1 C32.1 C70.1 C76.1 C77.1 C98.1 C119.1 L4.2 L5.2 L10.1 L12.1 R126.1 TP2.1 U4.1(AVDDH) U4.11(AVDDH) U4.17(AVDDH) U4.23(AVDDH) U4.33(AVDDH) U4.36(AVDDH) U4.88(AVDDH) U4.96(AVDDH) U4.106(AVDDH) U4.119(AVDDH)
AVDDL: C8.1 C9.1 C11.1 C12.1 C13.1 C22.1 C75.1 C80.1 C81.1 C82.1 C83.1 C85.1 C86.1 C88.1 C91.1 C93.1 C96.1 C97.1 C128.1 L1.2 L2.2 L13.1 L15.2 Q1.3(E) R121.1 TP1.1 U4.6(AVDDL) U4.14(AVDDL) U4.28(AVDDL) U4.34(AVDDL) U4.101(AVDDL) U4.111(AVDDL) U4.124(AVDDL)
DVDDIO: C3.1 C31.1 C67.1 C68.1 C73.1 D3.2 L11.1 L12.2 R2.2 R4.2 R9.1 R13.1 R15.1 R22.1 R97.2 R114.1 R116.2 R117.2 R120.2 R124.2 T5.1 U3.8(VCC) U4.18(DVDDIO) U4.70(DVDDIO)
DVDDIO_1: C53.1 C54.1 C55.1 C58.1 C64.1 L11.2 T4.1 U4.55(DVDDIO_1) U4.69(DVDDIO_1)
DVDDIO_2: C1.1 C50.1 C51.1 C52.1 C71.1 C84.1 L10.2 R82.2 T3.1 U1.8 U4.39(DVDDIO_2) U4.54(DVDDIO_2)
DVDDL: C61.1 C62.1 C63.1 C65.1 C66.1 C69.1 C74.1 C89.1 C127.1 L13.2 U4.21(DVDDL) U4.53(DVDDL) U4.71(DVDDL)
GND: C1.2 C2.2 C3.2 C4.2 C5.2 C6.2 C7.2 C8.2 C9.2 C10.2 C11.2 C12.2 C13.2 C14.2 C15.2 C16.2 C17.2 C18.2 C21.2 C22.2 C24.2 C25.2 C26.2 C27.2 C28.2 C29.2 C30.2 C31.2 C32.2 C33.2 C34.1 C35.2 C36.2 C38.2 C39.2 C44.2 C45.2 C46.1 C50.2 C51.2 C52.2 C53.2 C54.2 C55.2 C56.2 C57.2 C58.2 C60.2 C61.2 C62.2 C63.2 C64.2 C65.2 C66.2 C67.2 C68.2 C69.2 C70.2 C71.2 C72.2 C73.2 C74.2 C75.2 C76.2 C77.2 C78.2 C79.2 C80.2 C82.2 C83.2 C84.2 C85.2 C86.2 C87.2 C88.2 C89.2 C91.2 C93.2 C96.2 C97.2 C98.2 C99.2 C100.2 C101.2 C102.2 C103.2 C104.2 C105.2 C106.2 C107.2 C108.2 C109.2 C110.2 C111.2 C112.2 C113.2 C114.2 C115.2 C116.2 C117.2 C118.2 C120.1 C122.2 C123.2 C124.2 C125.1 C127.2 C128.2 D1.2(CATHODE) D2.1(ANODE) D4.1(ANODE) L6.2 L7.1 R23.2 R27.2 R39.2 R40.1 R41.2 R66.1 R67.2 R68.1 R69.2 R70.2 R71.1 R72.1 R73.1 R74.2 R75.1 R76.2 R77.1 R78.2 R79.2 R80.1 R81.1 R84.2 R98.1 R99.1 R104.2 R123.2 R125.1 R127.2 R143.2 T1.2 T1.4 T1.6 T1.8 T1.10 T1.12 T1.14 T1.16 T1.18 T1.20 T1.22 T1.24 T1.26 T1.28 T2.2 T2.4 T2.6 T2.8 T2.10 T2.12 T2.14 T2.16 T2.18 T2.20 T2.22 T2.24 T2.26 T2.28 T3.2 T4.2 T5.3 T6.2 T7.2 T10.1 U1.4 U2.4(GND) U2.9(GND) U3.1(A0) U3.2(A1) U3.3(A2) U3.4(GND) U4.12(AGND) U4.118(PLLGND) U4.EPAD(GND) U5.4(GND) U5.9(GND)
BS: C59.1 U2.1(BS)
COMP: C79.1 R119.1 U2.6(COMP)
E1_CRS: R37.2 T1.27 U4.56(M1M_CRS/GPIO13)
E1_DI0: T1.7 U4.65(M1P_TXD0/M1M_RXD0/RG1_RXD0/GPIO30)
E1_DI1: T1.5 U4.66(M1P_TXD1/M1M_RXD1/RG1_RXD1/GPIO31)
E1_DI2: T1.3 U4.67(M1P_TXD2/M1M_RXD2/RG1_RXD2/GPIO32)
E1_DI3: T1.1 U4.68(M1P_TXD3/M1M_RXD3/RG1_RXD3/GPIO33)
E1_DICLK: R28.2 T1.11
E1_DIDV: R37.1 T1.9 U4.64(M1P_TXEN/M1M_RXDV/RG1_RXCTL/GPIO29)
E1_DO0: RA1.8(R4) T1.17
E1_DO1: RA1.7(R4) T1.19
E1_DO2: RA1.6(R3) T1.21
E1_DO3: RA1.5(R3) T1.23
E1_DOEN: R30.2 T1.15
E1_GOCLK: R29.2 T1.13
E2_CRS: R142.2 R143.1 T2.27 U4.40(M2M_CRS/GPIO00)
E2_DI0: R133.2 S2.1 T2.7
E2_DI1: S1.1 T2.5 U4.50(M2P_TXD1/M2M_RXD1/RG2_RXD1/GPIO10)
E2_DI2: T2.3 U4.51(M2P_TXD2/M2M_RXD2/RG2_RXD2/GPIO11)
E2_DI3: T2.1 U4.52(M2P_TXD3/M2M_RXD3/RG2_RXD3/GPIO12)
E2_DICLK: R134.2 T2.11
E2_DIDV: R142.1 T2.9 U4.48(M2P_TXEN/M2M_RXDV/RG2_RXCTL/GPIO08)
E2_DO0: RA2.8(R4) S4.1 T2.17
E2_DO1: RA2.7(R4) T2.19
E2_DO2: RA2.6(R3) T2.21
E2_DO3: RA2.5(R3) T2.23
E2_DOEN: R136.2 S3.1 T2.15
E2_GOCLK: R135.2 T2.13
EN: R118.1 U2.7(EN)
FB: C81.2 R121.2 R123.1 U2.5(FB)
FGND: C34.2 C37.2 C40.2 C41.2 C42.2 C43.2 C46.2 C49.2 C120.2 C125.2 C126.2 PHJ1.43(FG) PHJ1.44(FG) PHJ1.45(FG) PHJ1.46(FG)
LX: C59.2 D2.2(CATHODE) L1.1 L2.1 R31.2 U2.3(LX)
nRESET: C72.1 D3.1 R120.1 T6.1 U4.91(nRESET)
P0LED0: R3.2 R12.1 U4.86(SMI_SEL/LED_CK/P0LED0/GPIO52)
P0LED1: R11.2 R102.1 U4.85(LED_DA/P0LED1/GPIO51)
P0LED2: R10.1 R113.2 U4.84(EN_PHY/P0LED2/GPIO50)
P0MDIA+: PHJ1.1(P0-1) X1.25(MX8-)
P0MDIA-: PHJ1.2(P0-2) X1.26(MX8+)
P0MDIAN: U4.98(P0MDIAN) X1.23(TD8+)
P0MDIAP: U4.97(P0MDIAP) X1.24(TD8-)
P0MDIB+: PHJ1.3(P0-3) X1.28(MX7-)
P0MDIB-: PHJ1.6(P0-6) X1.29(MX7+)
P0MDIBN: U4.100(P0MDIBN) X1.20(TD7+)
P0MDIBP: U4.99(P0MDIBP) X1.21(TD7-)
P0MDIC+: PHJ1.4(P0-4) X1.31(MX6-)
P0MDIC-: PHJ1.5(P0-5) X1.32(MX6+)
P0MDICN: U4.103(P0MDICN) X1.17(TD6+)
P0MDICP: U4.102(P0MDICP) X1.18(TD6-)
P0MDID+: PHJ1.7(P0-7) X1.34(MX5-)
P0MDID-: PHJ1.8(P0-8) X1.35(MX5+)
P0MDIDN: U4.105(P0MDIDN) X1.14(TD5+)
P0MDIDP: U4.104(P0MDIDP) X1.15(TD5-)
P1LED0: R14.2 R101.1 U4.82(MID29/P1LED0/GPIO48)
P1LED1: R105.2 R109.1 U4.83(P1LED1/GPIO49)
P1LED2: R16.1 R112.2 U4.81(RESERVED/P1LED2/GPIO47)
P1MDIA+: PHJ1.9(P1-1) X1.37(MX4-)
P1MDIA-: PHJ1.10(P1-2) X1.38(MX4+)
P1MDIAN: U4.108(P1MDIAN) X1.11(TD4+)
P1MDIAP: U4.107(P1MDIAP) X1.12(TD4-)
P1MDIB+: PHJ1.11(P1-3) X1.40(MX3-)
P1MDIB-: PHJ1.14(P1-6) X1.41(MX3+)
P1MDIBN: U4.110(P1MDIBN) X1.8(TD3+)
P1MDIBP: U4.109(P1MDIBP) X1.9(TD3-)
P1MDIC+: PHJ1.12(P1-4) X1.43(MX2-)
P1MDIC-: PHJ1.13(P1-5) X1.44(MX2+)
P1MDICN: U4.113(P1MDICN) X1.5(TD2+)
P1MDICP: U4.112(P1MDICP) X1.6(TD2-)
P1MDID+: PHJ1.15(P1-7) X1.46(MX1-)
P1MDID-: PHJ1.16(P1-8) X1.47(MX1+)
P1MDIDN: U4.115(P1MDIDN) X1.2(TD1+)
P1MDIDP: U4.114(P1MDIDP) X1.3(TD1-)
P2LED0: R19.2 R100.1 U4.79(DISAUTOLOAD/P2LED0/GPIO45)
P2LED1: R18.2 R111.1 U4.80(P2LED1/GPIO46)
P2LED2: R21.1 R108.2 U4.78(RESERVED/P2LED2/GPIO44)
P2MDIA+: PHJ1.17(P2-1) X2.25(MX8-)
P2MDIA-: PHJ1.18(P2-2) X2.26(MX8+)
P2MDIAN: U4.121(P2MDIAN) X2.23(TD8+)
P2MDIAP: U4.120(P2MDIAP) X2.24(TD8-)
P2MDIB+: PHJ1.19(P2-3) X2.28(MX7-)
P2MDIB-: PHJ1.22(P2-6) X2.29(MX7+)
P2MDIBN: U4.123(P2MDIBN) X2.20(TD7+)
P2MDIBP: U4.122(P2MDIBP) X2.21(TD7-)
P2MDIC+: PHJ1.20(P2-4) X2.31(MX6-)
P2MDIC-: PHJ1.21(P2-5) X2.32(MX6+)
P2MDICN: U4.126(P2MDICN) X2.17(TD6+)
P2MDICP: U4.125(P2MDICP) X2.18(TD6-)
P2MDID+: PHJ1.23(P2-7) X2.34(MX5-)
P2MDID-: PHJ1.24(P2-8) X2.35(MX5+)
P2MDIDN: U4.128(P2MDIDN) X2.14(TD5+)
P2MDIDP: U4.127(P2MDIDP) X2.15(TD5-)
P3LED0: R107.1 R110.1 U4.77(RESERVED/P3LED0/GPIO43)
P3LED1: R24.2 R26.1 U4.75(P3LED1/GPIO41)
P3LED2: R25.1 R103.1 U4.76(EN_PWRLIGHT/P3LED2/GPIO42)
P3MDIA+: PHJ1.25(P3-1) X2.37(MX4-)
P3MDIA-: PHJ1.26(P3-2) X2.38(MX4+)
P3MDIAN: U4.3(P3MDIAN) X2.11(TD4+)
P3MDIAP: U4.2(P3MDIAP) X2.12(TD4-)
P3MDIB+: PHJ1.27(P3-3) X2.40(MX3-)
P3MDIB-: PHJ1.30(P3-6) X2.41(MX3+)
P3MDIBN: U4.5(P3MDIBN) X2.8(TD3+)
P3MDIBP: U4.4(P3MDIBP) X2.9(TD3-)
P3MDIC+: PHJ1.28(P3-4) X2.43(MX2-)
P3MDIC-: PHJ1.29(P3-5) X2.44(MX2+)
P3MDICN: U4.8(P3MDICN) X2.5(TD2+)
P3MDICP: U4.7(P3MDICP) X2.6(TD2-)
P3MDID+: PHJ1.31(P3-7) X2.46(MX1-)
P3MDID-: PHJ1.32(P3-8) X2.47(MX1+)
P3MDIDN: U4.10(P3MDIDN) X2.2(TD1+)
P3MDIDP: U4.9(P3MDIDP) X2.3(TD1-)
P4LED0: R106.1 R115.1 U4.73(EEPROM_MOD/P4LED0/GPIO39)
P4LED1: R17.1 R65.2 U4.74(P4LED1/GPIO40)
P4LED2: R1.1 R20.2 U4.72(RESERVED/P4LED2/GPIO38)
P4MDIA+: PHJ1.33(P4-1) X3.13(MX4-)
P4MDIA-: PHJ1.34(P4-2) X3.14(MX4+)
P4MDIAN: U4.25(P4MDIAN) X3.11(TD4+)
P4MDIAP: U4.24(P4MDIAP) X3.12(TD4-)
P4MDIB+: PHJ1.35(P4-3) X3.16(MX3-)
P4MDIB-: PHJ1.38(P4-6) X3.17(MX3+)
P4MDIBN: U4.27(P4MDIBN) X3.8(TD3+)
P4MDIBP: U4.26(P4MDIBP) X3.9(TD3-)
P4MDIC+: PHJ1.36(P4-4) X3.19(MX2-)
P4MDIC-: PHJ1.37(P4-5) X3.20(MX2+)
P4MDICN: U4.30(P4MDICN) X3.5(TD2+)
P4MDICP: U4.29(P4MDICP) X3.6(TD2-)
P4MDID+: PHJ1.39(P4-7) X3.22(MX1-)
P4MDID-: PHJ1.40(P4-8) X3.23(MX1+)
P4MDIDN: U4.32(P4MDIDN) X3.2(TD1+)
P4MDIDP: U4.31(P4MDIDP) X3.3(TD1-)
PLLVDDL0: C15.1 C87.1 L15.1 U4.116(PLLVDDL)
SCK/SPI_CK: T5.4 U3.6(SCL) U4.93(SCK/SPIS_CK/GPIO54)
SDA/SPI_DI: R116.1 T5.2 U3.5(SDA) U4.94(SDA/SPIS_DI/GPIO55)
SPI_CS: R4.1 T9.1 U4.92(SPIS_nCSI/GPIO53)
SPI_DO: R2.1 T9.2 U4.95(SPIS_DO/GPIO56)
SS: C7.1 U2.8(SS)
VDC: C2.1 C4.1 C35.1 C36.1 C38.1 C39.1 C44.1 C45.1 C60.1 L8.1 L9.2 R118.2 R129.2 U2.2(Vin) U5.2(Vin)
N16768361: C47.2 C48.2 C49.1 C126.1 CN1.2 CN1.3 L6.1 L7.2
N16768397: C47.1 C48.1 CN1.1 L8.2 L9.1
N16787034: C103.1 C104.1 C105.1 C106.1 X2.1(TCT1) X2.4(TCT2) X2.7(TCT3) X2.10(TCT4)
N16787374: C107.1 C108.1 C109.1 C110.1 X2.13(TCT5) X2.16(TCT6) X2.19(TCT7) X2.22(TCT8)
N16789013: C41.1 C42.1 R51.2 R52.2 R53.2 R54.2 R55.2 R56.2 R57.2 R58.2 R63.1 R64.2
N16793377: C37.1 C40.1 R43.2 R44.2 R45.2 R46.2 R47.2 R48.2 R49.2 R50.2 R63.2
N16793383: C111.1 C112.1 C113.1 C114.1 X1.1(TCT1) X1.4(TCT2) X1.7(TCT3) X1.10(TCT4)
N16793456: C115.1 C116.1 C117.1 C118.1 X1.13(TCT5) X1.16(TCT6) X1.19(TCT7) X1.22(TCT8)
N16794554: C99.1 C100.1 C101.1 C102.1 X3.1(TCT1) X3.4(TCT2) X3.7(TCT3) X3.10(TCT4)
N16796884: R50.1 X1.48(CMT1)
N16797605: R49.1 X1.45(CMT2)
N16797687: R48.1 X1.42(CMT3)
N16797771: R47.1 X1.39(CMT4)
N16797857: R46.1 X1.36(CMT5)
N16797945: R45.1 X1.33(CMT6)
N16798035: R44.1 X1.30(CMT7)
N16798127: R43.1 X1.27(CMT8)
N16798804: R58.1 X2.48(CMT1)
N16798883: R57.1 X2.45(CMT2)
N16798965: R56.1 X2.42(CMT3)
N16799049: R55.1 X2.39(CMT4)
N16799135: R54.1 X2.36(CMT5)
N16799223: R53.1 X2.33(CMT6)
N16799313: R52.1 X2.30(CMT7)
N16799405: R51.1 X2.27(CMT8)
N16802185: C43.1 R59.2 R60.2 R61.2 R62.2 R64.1
N16802239: R61.1 X3.21(MCT2)
N16802329: R60.1 X3.18(MCT3)
N16802421: R59.1 X3.15(MCT4)
N16821539: LED1.1 R12.2 R13.2 R72.2
N16822789: LED1.2 R3.1 R74.1
N16822819: LED1.3 R10.2 R73.2 R102.2
N16822970: LED2.1 R15.2 R80.2 R101.2
N16822972: LED2.3 R16.2 R81.2 R109.2
N16823052: LED3.1 R22.2 R77.2 R100.2
N16823054: LED3.3 R21.2 R69.1 R111.2
N16823098: LED3.4 R18.1 R79.1 R108.1
N16823139: LED4.3 R25.2 R26.2 R66.2
N16823225: LED5.1 R9.2 R98.2 R115.2
N16858351: R117.1 U3.7(WP)
N16877502: LED3.2 R19.1 R78.1
N16986254: LED2.2 R14.1 R70.1
N16986516: LED2.4 R71.2 R105.1 R112.1
N17080423: R144.2 U4.89(XTALO)
N17080567: C57.1 U4.90(XTALI) Y1.1
N17081299: C56.1 R144.1 Y1.2
N17250511: LED4.4 R24.1 R67.1 R103.2
N17252813: LED5.2 R104.1 R106.2
N17314726: LED1.4 R11.1 R75.2 R113.1
N17383937: C121.2 D4.2(CATHODE) L4.1 L5.1 R42.2 U5.3(LX)
N17385467: C119.2 R126.2 R127.1 U5.5(FB)
N17386140: R129.1 U5.7(EN)
N17387342: C122.1 R128.2
N17387490: C123.1 R128.1 U5.6(COMP)
N17388746: C124.1 U5.8(SS)
N17389803: C121.1 U5.1(BS)
N17400156: C78.1 R119.2
N17440327: LED5.4 R20.1 R27.1 R65.1
N17467657: R62.1 X3.24(MCT1)
N17481673: RA1.2(R1) U4.59(M1P_RXD1/M1M_TXD1/RG1_TXD1/GPIO21)
N17481812: RA1.1(R1) U4.60(M1P_RXD0/M1M_TXD0/RG1_TXD0/GPIO22)
N17481951: R30.1 U4.61(M1P_RXDV/M1M_TXEN/RG1_TXCTL/GPIO23)
N17482090: R29.1 U4.62(M1P_RXCLK/M1M_TXCLK/RG1_TXCLK/GPIO24)
N17512717: R28.1 U4.63(M1P_TXCLK/M1M_RXCLK/RG1_RXCLK/GPIO28)
N17518228: S1.2 U1.1
N17518250: S2.2 U1.2
N17518418: R82.1 U1.7
N17518440: S4.2 U1.6
N17519498: S3.2 U1.5
N17531826: Q1.1(B) U4.37(RESERVED)
N17532181: R99.2 U1.3
N17534885: C17.1 C18.1 Q1.2(C) Q1.4(C) T7.1
N17549730: LED4.1 R68.2 R110.2 R114.2
N17549818: LED4.2 R76.1 R107.2
N17599766: RA1.3(R2) U4.58(M1P_RXD2/M1M_TXD2/RG1_TXD2/GPIO20)
N17793293: C6.1 R31.1
N17852042: D1.1(ANODE) R97.1
N17934663: C33.1 R42.1
N18172592: RA1.4(R2) U4.57(M1P_RXD3/M1M_TXD3/RG1_TXD3/GPIO19)
N18182398: RA2.4(R2) U4.41(M2P_RXD3/M2M_TXD3/RG2_TXD3/GPIO01)
N18182536: RA2.3(R2) U4.42(M2P_RXD2/M2M_TXD2/RG2_TXD2/GPIO02)
N18182674: RA2.2(R1) U4.43(M2P_RXD1/M2M_TXD1/RG2_TXD1/GPIO03)
N18182817: RA2.1(R1) U4.44(M2P_RXD0/M2M_TXD0/RG2_TXD0/GPIO04)
N18182960: R136.1 U4.45(M2P_RXDV/M2M_TXEN/RG2_TXCTL/GPIO05)
N18183103: R135.1 U4.46(M2P_RXCLK/M2M_TXCLK/RG2_TXCLK/GPIO06)
N18199884: R39.1 U4.13(MDIREF)
N18199903: R41.1 U4.20(GPIO58/DIS_LPD)
N18199928: R125.2 U4.15(RTT1)
N18199934: R124.1 U4.19(GPIO57/INTERRUPT)
N18199948: R40.2 U4.16(RTT2)
N18212445: R133.1 U4.49(M2P_TXD0/M2M_RXD0/RG2_RXD0/GPIO09)
N18233162: R83.1 U4.117(ATESTCK)
N18233300: R83.2 T10.2
N18304896: R134.1 U4.47(M2P_TXCLK/M2M_RXCLK/RG2_RXCLK/GPIO07)
N18379143: R84.1 U4.35(RESERVED)
N18392071: LED5.3 R1.2 R17.2 R23.1

Not connected (* = marked no-connect by the designer): PHJ1 41(NC) 42(NC); T1 25*; T2 25*; U4 22(NC)* 38(NC)* 87(NC)*

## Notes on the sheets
sheet 1
- RTL8367RB-VB (14x14 LQFP128 EPAD) PCB-P4L
  Demo-Board Block Diagram
- REVISION HISTORY
- Release
  Date
- Summary
- Revision
- LED
- v.1.0
- 2011/12/06
- RTL8367RB v1.0 PCB-P4L First Release
- EEPROM
- (Optional)
- v.1.01
- 2011/12/06
- RTL8367RB-VB- First Release
- XTAL
  25M
- v.1.02
- 2015/11/13
- Add damping resistor R144 on XTALO trace
- LED
- SDA
- SDA
- SCK
- SCK
- RTL8367RB-VB
  LQFP128EP
  (14x14)
- nRESET
- nRESET
- 80mm
- MDI 0
- MDI 1
- MDI 2
- MDI 3
- MDI 4
- X'Former &
  Phone Jack
- X'Former &
  Phone Jack
- X'Former &
  Phone Jack
- DC
- Jack
- 100mm
sheet 2
- Max Load: VDDL 800mA (continue)
- 1.1V = 0.92V x (1 + 2K / 10K)
- Adjust R121, R123 to make sure chip side voltage is 1.1V
  (Due to 2Layer design, need to consider the tramsmition loss)
- 5V ~ 7.5V VDC 1A
- (120ohm@100MHz/2A, DCR 0.1ohm)
- Power LED
- Max Load: VDDH 350mA (continue)
- Vout  = 0.92* (1+26.1K/10K)
sheet 3
- Extension Port 1
- Pin
  No.
- Extension
  Interface
- RGMII
- MII
- MII
- PIN82 P1LED0 / RESERVED: Must Pull Low
- PIN86 P0LED0 / SMI_SEL:
- 56 E1_CRS             M1M_CRS
- MAC Mode
- PHY Mode
- PIN76 P3LED2 / EN_PWRLIGHT:
- ** Pull Up: I2C Interface (Slave).
- Pull Down: MII Management
  Interface(Slave).
- 57 E1_DO3   RG1_TXD3  M1M_TXD3  M1P_RXD3
- **Pull Up: Enable LED Power on Light
- 58 E1_DO2   RG1_TXD2  M1M_TXD2  M1P_RXD2
- Pull Down: Disable LED Power on Light
- 59 E1_DO1   RG1_TXD1  M1M_TXD1  M1P_RXD1
- 60 E1_DO0   RG1_TXD0  M1M_TXD0  M1P_RXD0
- PIN77 P3LED0 / RESERVED: Must Pull Low
- PIN84 P0LED2 / EN_PHY:
- 61 E1_DOEN  RG1_TXCTL M1M_TXEN  M1P_RXDV
- Pull Up:  Enable embedded PHY
- 62 E1_GCLK  RG1_TXCLK M1M_TXCLK M1P_RXCLK
- 63 E1_DICLK RG1_RXCLK M1M_RXCLK M1P_TXCL
- PIN22 RESERVED: Must Pull High or Keep
  Floating
- ** Pull Down: Disable embedded PHY
- 64 E1_DIDV  RG1_RXCTL M1M_RXDV  M1P_TXEN
- PIN79 P2LED0 / DISAUTOLOAD
- 65 E1_DI0   RG1_RXD0  M1M_RXD0  M1P_TXD0
- PIN81 P1LED2 / RESERVED: Must Pull
  High or Keep Floating
- ** Pull Low: Enable Auto load EEPROM
- 66 E1_DI1   RG1_RXD1  M1M_RXD1  M1P_TXD1
- Pull High: Disable Auto load EEPROM
- 67 E1_DI2   RG1_RXD2  M1M_RXD2  M1P_TXD2
- 68 E1_DI3   RG1_RXD3  M1M_RXD3  M1P_TXD3
- PIN40 RESERVED: Must Pull Low
- PIN78 P2LED2 / DIS_8051
- Pull Low: Enable 8051
- Extension Port 2
- ** Pull High: Disable 8051
- 41 E2_DO3   RG2_TXD3  M2M_TXD3  M2P_RXD3
- 42 E2_DO2   RG2_TXD2  M2M_TXD2  M2P_RXD2
- PIN73 P4LED0 / EEPROM_MOD
- 43 E2_DO1   RG2_TXD1  M2M_TXD1  M2P_RXD1
- ** Pull Low: 24C02~24C16
- 44 E2_DO0   RG2_TXD0  M2M_TXD0  M2P_RXD0
- Pull High: 24C32~24C256
- 45 E2_DOEN  RG2_TXCTL M2M_TXEN  M2P_RXDV
- 46 E2_GCLK  RG2_TXCLK M2M_TXCLK M2P_RXCLK
- PIN72 P4LED2 / DIS_SPI:
- 47 E2_DICLK RG2_RXCLK M2M_RXCLK M2P_TXCLK
- Pull Low: Enable SPI Slave
- 48 E2_DIDV  RG2_RXCTL M2M_RXDV  M2P_TXEN
- ** Pull High: Disable SPI Slave
- 49 E2_DI0   RG2_RXD0  M2M_RXD0  M2P_TXD0
- 50 E2_DI1   RG2_RXD1  M2M_RXD1  M2P_TXD1
- PIN20 DIS_LPD:
- 51 E2_DI2   RG2_RXD2  M2M_RXD2  M2P_TXD2
- 52 E2_DI3   RG2_RXD3  M2M_RXD3  M2P_TXD3
- ** Pull High: Disable Loop Detection
- Pull Low: Enable Loop Detection
- RESERVED for
  Internal use
- RESERVED for
  Internal use
- 3.3V
- SDA/SPI_DI
- GND
- SCK/SPI_CK
- SPI_CS
- SPI_DO
sheet 4
- X'Formre Central Tap at Primary
  Side must tie with each other.
- Can't tie together
  between different ports.
sheet 5
- Port 3 LED
- Port 0 LED
- P0LED0 / SMI_SEL
- P0LED2 / EN_PHY:
- P3LED0 / RESERVED: Must
  Pull Low
- P3LED2 / EN_PWRLIGHT:
- ** Pull Up: I2C Interface(Slave)
- Pull Up:  Enable embedded PHY
- Pull Up: Enable LED Power on Light
- Pull Down: MII Management
  Interface(Slave)
- ** Pull Down: Disable embedded PHY
- **Pull Down: Disable LED Power on Light
- Port 4 LED
- Port 1 LED
- P1LED0 / MID29
- P1LED2 / RESERVED: Must Pull High
  or Keep Floating
- P4LED0 / EEPROM_MOD
- P4LED2 / DIS_SPI:
- Pull Up: MII Management Interface
  PHY ID is 29
- ** Pull Low: 24C02~24C16
- Pull Low: Enable SPI Slave
- ** Pull Down: MII Management
  Interface PHY ID is 0
- Pull High: 24C32~24C256
- **Pull High: Disable SPI Slave
- Port 2 LED
- P2LED0 / DISAUTOLOAD
- P2LED2 / DIS_8051
- ** Pull Low: Enable Auto load EEPROM
- Pull Low: Enable 8051
- Pull High: Disable Auto load EEPROM
- ** Pull High: Disable 8051
